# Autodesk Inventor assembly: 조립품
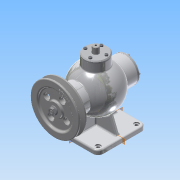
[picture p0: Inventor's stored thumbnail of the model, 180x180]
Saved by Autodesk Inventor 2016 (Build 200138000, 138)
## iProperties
Created: 2017-01
Part Number: 조립품
Material: 일반
Document SubType Name: Assembly
Designer: Administrator
Author: Administrator
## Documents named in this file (18)
- C:\Users\Administrator\Desktop\470130V1006\470130V1006\조립품.iam
- C:\Users\Administrator\Desktop\470130V1006\470130V1006\본체.ipt
- C:\Users\Administrator\Desktop\470130V1006\470130V1006\편심축.ipt
- C:\Users\Administrator\Desktop\470130V1006\470130V1006\V-벨트풀리.ipt
- C:\Users\Administrator\Desktop\470130V1006\470130V1006\너트 M8.ipt
- C:\Users\Administrator\Desktop\470130V1006\470130V1006\키 4 x 4 x 12.ipt
- C:\Users\Administrator\Desktop\470130V1006\470130V1006\베어링- 6202.ipt
- KS B 2023 - 6202 - 15 x 35 x 11 - 7.8.ipt
- C:\Users\Administrator\Desktop\470130V1006\470130V1006\부시.ipt
- C:\Users\Administrator\Desktop\470130V1006\470130V1006\슬라이드.ipt
- C:\Users\Administrator\Desktop\470130V1006\470130V1006\멈춤링- 35x1.6.ipt
- KS B 1336 - 35x1.6.ipt
- C:\Users\Administrator\Desktop\470130V1006\470130V1006\멈춤링- 15 x 1.ipt
- C:\Users\Administrator\Desktop\470130V1006\470130V1006\뒤커버.ipt
- C:\Users\Administrator\Desktop\470130V1006\470130V1006\상부커버.ipt
- C:\Users\Administrator\Desktop\470130V1006\470130V1006\앞커버.ipt
- C:\Users\Administrator\Desktop\470130V1006\470130V1006\볼트 M4 x 16.ipt
- C:\Users\Administrator\Desktop\470130V1006\470130V1006\볼트 M4 x 12.ipt
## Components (16 placed, 5 different names)
1. V-벨트풀리:1
2. KS B 2023 - 6202 - 15 x 35 x 11 - 7.8:1
3. KS B 1336 - 35x1.6:1
4. KS B 2023 - 6202 - 15 x 35 x 11 - 7.8:2
5. ISO 4762 M4 x 16:1
6. ISO 4762 M4 x 16:2
7. ISO 4762 M4 x 16:3
8. ISO 4762 M4 x 16:4
9. ISO 4762 M4 x 16:5
10. ISO 4762 M4 x 16:6
11. ISO 4762 M4 x 16:7
12. ISO 4762 M4 x 16:8
13. KS B 1021 - 에 따름 ISO 1207 - 미터 A  M 4 x 12:1
14. KS B 1021 - 에 따름 ISO 1207 - 미터 A  M 4 x 12:2
15. KS B 1021 - 에 따름 ISO 1207 - 미터 A  M 4 x 12:3
16. KS B 1021 - 에 따름 ISO 1207 - 미터 A  M 4 x 12:4
